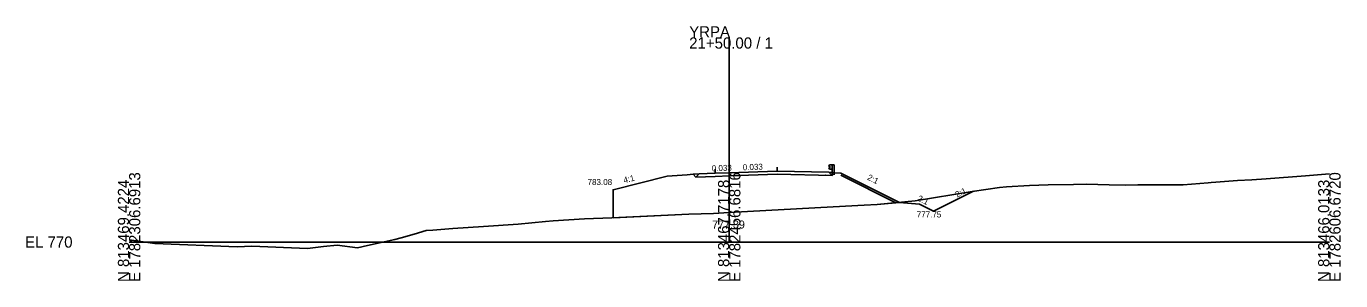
# Model space of a CAD drawing. Extents: x -26 to 2603, y -14 to 9545.
# Drawn here: x 974.3 to 1302.8, y 1490.3 to 1554 of the extents above; entities that cross this region are included whole.
import ezdxf

# ---------------------------------------------------------------- set-up
doc = ezdxf.new("R2010")
doc.units = 0
for name, color, linetype in [('Exist Cross Section Cell', 7, 'Continuous'), ('Exist XS Center Line Elevation Label', 7, 'Continuous'), ('Exist XS Ground Line', 7, 'Continuous'), ('Prop XS DDE', 7, 'Continuous'), ('Prop XS Ditch Standard Text', 7, 'Continuous'), ('Prop XS Dump Level', 7, 'Continuous'), ('Prop XS Earthwork Shape', 7, 'Continuous'), ('Prop XS EOT Tick Mark', 7, 'Continuous'), ('Prop XS Finish Grade', 7, 'Continuous'), ('Prop XS Finish Grade Earthwork', 7, 'Continuous'), ('Prop XS Finish Grade Paved Shoulder', 7, 'Continuous'), ('Prop XS Finish Grade Pavement', 7, 'Continuous'), ('Prop XS Guardrail', 7, 'Continuous'), ('Prop XS Hydro Fill Slope Data', 7, 'Continuous'), ('Prop XS Pvmt Edge Slope', 7, 'Continuous'), ('Prop XS SE Text', 7, 'Continuous'), ('Prop XS Side Slope Text', 7, 'Continuous'), ('Prop XS Subgrade Earthwork', 7, 'Continuous')]:
    doc.layers.add(name, color=color, linetype=linetype)

msp = doc.modelspace()

# ---------------------------------------------------------------- linework, layer by layer
at = {"layer": 'Exist Cross Section Cell'}
for p, q in [((1150, 1500), (1150, 1551.24)), ((1000, 1500), (1150, 1500)), ((1150, 1500), (1300, 1500))]:
    msp.add_line(p, q, dxfattribs=at)
at = {"layer": 'Exist XS Ground Line'}
for p, q in [((1263.45, 1514.36), (1269.7, 1514.83)), ((1269.7, 1514.83), (1270.45, 1514.9)), ((1270.45, 1514.9), (1271.6, 1515.01)), ((1271.6, 1515.01), (1277.05, 1515.38)), ((1277.05, 1515.38), (1280.61, 1515.54)), ((1280.61, 1515.54), (1284.24, 1515.8)), ((1284.24, 1515.8), (1294.08, 1516.54)), ((1294.08, 1516.54), (1300, 1517.08)), ((1196.45, 1510.3), (1210.71, 1512.68)), ((1210.71, 1512.68), (1217.58, 1513.62)), ((1217.58, 1513.62), (1219.3, 1513.84)), ((1219.3, 1513.84), (1225.06, 1514.12)), ((1225.06, 1514.12), (1229.68, 1514.34)), ((1229.68, 1514.34), (1236.05, 1514.44)), ((1236.05, 1514.44), (1239.29, 1514.49)), ((1239.29, 1514.49), (1244.99, 1514.34)), ((1244.99, 1514.34), (1249.01, 1514.25)), ((1249.01, 1514.25), (1252.1, 1514.29)), ((1252.1, 1514.29), (1263.45, 1514.36)), ((1150, 1507.39), (1175.98, 1508.81)), ((1175.98, 1508.81), (1183.71, 1509.21)), ((1183.71, 1509.21), (1187, 1509.42)), ((1187, 1509.42), (1196.45, 1510.3)), ((1097.28, 1504.51), (1104.07, 1505.16)), ((1104.07, 1505.16), (1106, 1505.28)), ((1106, 1505.28), (1109.94, 1505.55)), ((1109.94, 1505.55), (1113.85, 1505.82)), ((1113.85, 1505.82), (1120.7, 1506.09)), ((1120.7, 1506.09), (1139.87, 1506.97)), ((1139.87, 1506.97), (1146.11, 1507.18)), ((1146.11, 1507.18), (1150, 1507.39)), ((1068, 1501.03), (1071.26, 1501.96)), ((1071.26, 1501.96), (1074.25, 1502.89)), ((1074.25, 1502.89), (1075.93, 1502.97)), ((1075.93, 1502.97), (1080.9, 1503.38)), ((1080.9, 1503.38), (1088.6, 1503.9)), ((1088.6, 1503.9), (1097.28, 1504.51)), ((1000, 1500.52), (1006.47, 1499.63)), ((1006.47, 1499.63), (1026.98, 1498.8)), ((1026.98, 1498.8), (1030.66, 1499)), ((1030.66, 1499), (1044.61, 1498.42)), ((1044.61, 1498.42), (1048.62, 1498.87)), ((1048.62, 1498.87), (1052.05, 1499.25)), ((1052.05, 1499.25), (1057.07, 1498.59)), ((1057.07, 1498.59), (1059.58, 1499.12)), ((1059.58, 1499.12), (1066.4, 1500.66)), ((1066.4, 1500.66), (1068, 1501.03))]:
    msp.add_line(p, q, dxfattribs=at)
at = {"layer": 'Prop XS DDE'}
for p, q in [((1201.08, 1507.75), (1211.02, 1512.72)), ((1192.55, 1509.94), (1197.55, 1509.52)), ((1197.55, 1509.52), (1201.08, 1507.75))]:
    msp.add_line(p, q, dxfattribs=at)
at = {"layer": 'Prop XS Dump Level'}
for p, q in [((1146.5, 1517.24), (1150, 1517.35)), ((1150, 1517.35), (1162, 1517.75))]:
    msp.add_line(p, q, dxfattribs=at)
at = {"layer": 'Prop XS Earthwork Shape'}
msp.add_lwpolyline([(1139.5, 1516.86), (1140.98, 1516.98), (1141.68, 1516.28), (1146.53, 1516.45), (1150.03, 1516.56), (1162.01, 1516.96), (1175.72, 1516.69), (1176.41, 1517.37), (1177.91, 1517.25), (1192.55, 1509.94), (1187, 1509.42), (1183.71, 1509.21), (1175.98, 1508.81), (1150, 1507.39), (1146.11, 1507.18), (1139.87, 1506.97), (1120.97, 1506.1), (1120.97, 1513.08), (1134.5, 1516.46)], close=True, dxfattribs=at)
at = {"layer": 'Prop XS EOT Tick Mark'}
for p, q in [((1146.5, 1517.24), (1146.5, 1518.24)), ((1162, 1517.75), (1162, 1518.75))]:
    msp.add_line(p, q, dxfattribs=at)
at = {"layer": 'Prop XS Finish Grade'}
for p, q in [((1142.5, 1517.1), (1140.98, 1516.98)), ((1174.91, 1517.49), (1176.41, 1517.37))]:
    msp.add_line(p, q, dxfattribs=at)
at = {"layer": 'Prop XS Finish Grade Earthwork'}
for p, q in [((1134.5, 1516.46), (1120.97, 1513.08)), ((1134.5, 1516.46), (1139.5, 1516.86)), ((1139.5, 1516.86), (1140.98, 1516.98)), ((1176.41, 1517.37), (1177.91, 1517.25)), ((1177.91, 1517.25), (1192.55, 1509.94)), ((1120.97, 1513.08), (1120.97, 1506.1))]:
    msp.add_line(p, q, dxfattribs=at)
at = {"layer": 'Prop XS Finish Grade Paved Shoulder'}
for p, q in [((1146.5, 1517.24), (1142.5, 1517.1)), ((1162, 1517.75), (1174.91, 1517.49))]:
    msp.add_line(p, q, dxfattribs=at)
at = {"layer": 'Prop XS Finish Grade Pavement'}
for p, q in [((1146.5, 1517.24), (1150, 1517.35)), ((1150, 1517.35), (1162, 1517.75))]:
    msp.add_line(p, q, dxfattribs=at)
at = {"layer": 'Prop XS Guardrail'}
for p, q in [((1174.94, 1519.15), (1174.91, 1519.09)), ((1174.91, 1519.09), (1174.94, 1519.03)), ((1174.94, 1518.54), (1174.91, 1518.48)), ((1174.91, 1518.48), (1174.94, 1518.42)), ((1175.23, 1519.35), (1174.94, 1519.15)), ((1174.94, 1519.03), (1175.23, 1518.83)), ((1175.23, 1518.74), (1174.94, 1518.54)), ((1174.94, 1518.42), (1175.23, 1518.22)), ((1175.73, 1519.35), (1175.23, 1519.35)), ((1175.23, 1518.83), (1175.23, 1518.74)), ((1175.23, 1518.22), (1175.73, 1518.22)), ((1176.23, 1519.35), (1175.73, 1519.35)), ((1175.73, 1519.35), (1175.73, 1516.85)), ((1176.23, 1516.85), (1176.23, 1519.35))]:
    msp.add_line(p, q, dxfattribs=at)
at = {"layer": 'Prop XS Hydro Fill Slope Data'}
for p, q in [((1134.5, 1516.46), (1120.97, 1513.08)), ((1177.91, 1516.72), (1191.65, 1509.85))]:
    msp.add_line(p, q, dxfattribs=at)
at = {"layer": 'Prop XS Pvmt Edge Slope'}
for p, q in [((1142.5, 1517.1), (1141.68, 1516.28)), ((1174.91, 1517.49), (1175.72, 1516.69))]:
    msp.add_line(p, q, dxfattribs=at)
at = {"layer": 'Prop XS Subgrade Earthwork'}
for p, q in [((1141.68, 1516.28), (1140.98, 1516.98)), ((1146.53, 1516.45), (1141.68, 1516.28)), ((1146.53, 1516.45), (1150.03, 1516.56)), ((1150.03, 1516.56), (1162.01, 1516.96)), ((1162.01, 1516.96), (1175.72, 1516.69)), ((1175.72, 1516.69), (1176.41, 1517.37))]:
    msp.add_line(p, q, dxfattribs=at)

# ---------------------------------------------------------------- texts
at = {"layer": 'Exist Cross Section Cell'}
for s, p in [('YRPA', (1140, 1551.24)), ('21+50.00 / 1', (1140, 1548.44)), ('EL 770', (974, 1498.6))]:
    msp.add_text(s, height=2.8, dxfattribs=at).set_placement(p)
for s, p in [('N 813469.4224', (1000, 1490)), ('E 1782306.6913', (1002.8, 1490)), ('N 813467.7178', (1150, 1490)), ('E 1782456.6816', (1152.8, 1490)), ('N 813466.0133', (1300, 1490)), ('E 1782606.6720', (1302.8, 1490))]:
    msp.add_text(s, height=2.8, rotation=90, dxfattribs=at).set_placement(p)
at = {"layer": 'Exist XS Center Line Elevation Label'}
msp.add_text('777.39', height=2, dxfattribs=at).set_placement((1145.73, 1503.39))
at = {"layer": 'Prop XS Ditch Standard Text'}
for s, p in [('783.08', (1114.6, 1514.28)), ('777.75', (1196.87, 1506.16))]:
    msp.add_text(s, height=1.5, dxfattribs=at).set_placement(p)
at = {"layer": 'Prop XS Dump Level'}
for p in [(1134.5, 1516.42), (1174, 1516.99)]:
    msp.add_text('Case4', height=0.04, dxfattribs=at).set_placement(p)
at = {"layer": 'Prop XS SE Text'}
for p in [(1145.66, 1517.71), (1153.41, 1517.97)]:
    msp.add_text('0.033', height=1.5, rotation=1.9059, dxfattribs=at).set_placement(p)
at = {"layer": 'Prop XS Side Slope Text'}
for s, rotation, p in [('4:1', 14.0362, (1123.76, 1514.72)), ('2:1', 333.4349, (1184.37, 1515.7)), ('2:1', 333.4349, (1196.89, 1510.46)), ('2:1', 26.5651, (1206.95, 1511.11))]:
    msp.add_text(s, height=1.5, rotation=rotation, dxfattribs=at).set_placement(p)

doc.saveas('drawing.dxf')
